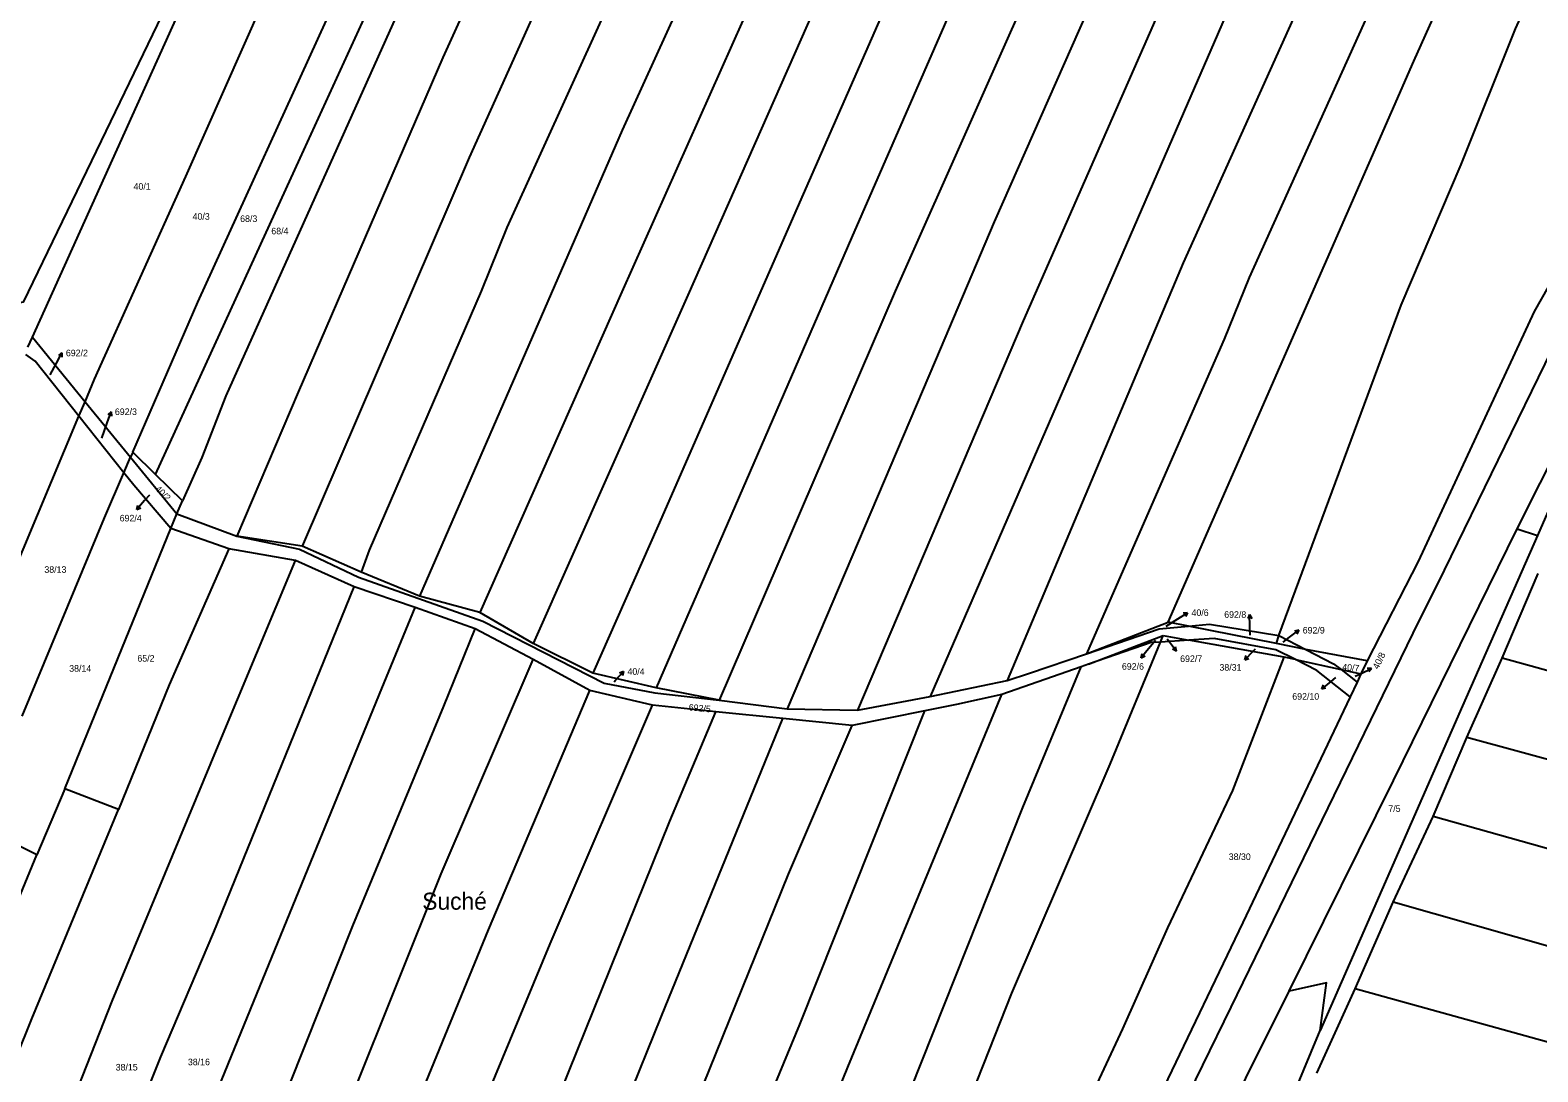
# Model space of a CAD drawing. Extents: x -7483133 to -743169, y -11317770 to -1127091.
# Drawn here: x -746258 to -745868.6, y -1131128.4 to -1130859.4 of the extents above; entities that cross this region are included whole.
import ezdxf

# ---------------------------------------------------------------- set-up
doc = ezdxf.new("R2010")
doc.units = 0
for name, color, linetype in [('Hranice parcel', 7, 'Continuous'), ('Parcelní čísla', 7, 'Continuous'), ('Pop  PČ popisy', 7, 'Continuous')]:
    doc.layers.add(name, color=color, linetype=linetype)

msp = doc.modelspace()

# ---------------------------------------------------------------- linework, layer by layer
at = {"layer": 'Hranice parcel'}
for p, q in [((-746257.43, -1130938.7), (-746218.07, -1130851.43)), ((-746257.43, -1130938.7), (-746218.07, -1130851.43)), ((-745845.23, -1130936.04), (-745868.71, -1130989.88)), ((-746258.58, -1130941.26), (-746257.43, -1130938.7)), ((-746258.58, -1130941.26), (-746257.43, -1130938.7)), ((-746257.43, -1130938.7), (-746243.76, -1130955.41)), ((-746245.4, -1130959.13), (-746243.76, -1130955.41)), ((-746243.76, -1130955.41), (-746232.08, -1130969.68)), ((-746275.51, -1131030.97), (-746245.4, -1130959.13)), ((-746233.82, -1130973.73), (-746245.4, -1130959.13)), ((-746231.52, -1130968.38), (-746232.08, -1130969.68)), ((-746225.59, -1130974.19), (-746231.52, -1130968.38)), ((-746233.82, -1130973.73), (-746232.08, -1130969.68)), ((-746232.08, -1130969.68), (-746220.11, -1130984.31)), ((-746218.64, -1130981), (-746225.59, -1130974.19)), ((-746220.11, -1130984.31), (-746218.64, -1130981)), ((-746249.08, -1131055.3), (-746221.66, -1130988.08)), ((-746221.66, -1130988.08), (-746220.11, -1130984.31)), ((-746206.72, -1130993.33), (-746221.66, -1130988.08)), ((-746220.11, -1130984.31), (-746204.63, -1130990.11)), ((-746187.79, -1130992.68), (-746204.63, -1130990.11)), ((-745873.92, -1130988.21), (-745868.71, -1130989.88)), ((-746189.47, -1130996.38), (-746206.72, -1130993.33)), ((-746172.51, -1130999.37), (-746187.79, -1130992.68)), ((-746174.36, -1131003.15), (-746189.47, -1130996.38)), ((-746157.46, -1131005.59), (-746172.51, -1130999.37)), ((-745877.83, -1131021.56), (-745868.53, -1130999.77)), ((-746158.58, -1131008.54), (-746174.36, -1131003.15)), ((-746141.88, -1131009.81), (-746157.46, -1131005.59)), ((-746143.06, -1131014.03), (-746158.58, -1131008.54)), ((-746128.13, -1131017.8), (-746141.88, -1131009.81)), ((-746128.09, -1131021.91), (-746143.06, -1131014.03)), ((-745985.17, -1131020.45), (-745964.11, -1131012.31)), ((-745958.88, -1131013.33), (-745964.11, -1131012.31)), ((-745936.14, -1131017.79), (-745958.88, -1131013.33)), ((-746112.7, -1131025.49), (-746128.13, -1131017.8)), ((-745984.64, -1131023.14), (-745965.38, -1131015.77)), ((-745966.08, -1131017.43), (-745965.38, -1131015.77)), ((-745958.8, -1131016.95), (-745966.08, -1131017.43)), ((-745965.38, -1131015.77), (-745958.8, -1131016.95)), ((-745934.1, -1131021.36), (-745958.8, -1131016.95)), ((-745936.14, -1131017.79), (-745935.5, -1131015.73)), ((-745928.53, -1131019.33), (-745936.14, -1131017.79)), ((-745935.5, -1131015.73), (-745928.53, -1131019.33)), ((-745912.67, -1131022.25), (-745928.53, -1131019.33)), ((-746113.48, -1131029.98), (-746128.09, -1131021.91)), ((-745984.64, -1131023.14), (-745986.56, -1131023.8)), ((-745931.24, -1131021.98), (-745934.1, -1131021.36)), ((-745931.24, -1131021.98), (-745919.43, -1131024.53)), ((-745912.67, -1131022.25), (-745914.31, -1131025.61)), ((-745886.94, -1131042.08), (-745877.83, -1131021.56)), ((-745753.49, -1131055.99), (-745877.83, -1131021.56)), ((-746096.35, -1131029.25), (-746112.7, -1131025.49)), ((-745986.56, -1131023.8), (-746007.08, -1131031)), ((-745919.43, -1131024.53), (-745914.31, -1131025.61)), ((-745919.43, -1131024.53), (-745915.31, -1131027.82)), ((-745914.31, -1131025.61), (-745915.31, -1131027.82)), ((-746097.27, -1131033.75), (-746113.48, -1131029.98)), ((-746080.02, -1131032.46), (-746096.35, -1131029.25)), ((-746025.56, -1131031.47), (-746005.67, -1131027.4)), ((-745915.31, -1131027.82), (-745917.09, -1131031.6)), ((-746080.96, -1131035.48), (-746097.27, -1131033.75)), ((-746080.02, -1131032.46), (-746062.49, -1131034.7)), ((-746062.49, -1131034.7), (-746044.37, -1131035)), ((-746044.37, -1131035), (-746025.56, -1131031.47)), ((-746063.64, -1131037.14), (-746080.96, -1131035.48)), ((-746045.68, -1131039.01), (-746063.64, -1131037.14)), ((-746026.94, -1131035.21), (-746045.68, -1131039.01)), ((-745895.67, -1131062.5), (-745886.94, -1131042.08)), ((-745759.13, -1131076.92), (-745886.94, -1131042.08)), ((-746249.08, -1131055.3), (-746256.26, -1131072.39)), ((-746235.16, -1131060.66), (-746249.08, -1131055.3)), ((-746256.26, -1131072.39), (-746271.75, -1131064.63)), ((-745905.99, -1131084.62), (-745895.67, -1131062.5)), ((-745915.82, -1131106.97), (-745905.99, -1131084.62)), ((-745925.69, -1131128.75), (-745915.82, -1131106.97))]:
    msp.add_line(p, q, dxfattribs=at)
for points in [[(-746057.93, -1130494.49), (-746062.35, -1130503.85), (-746105.8, -1130595.89), (-746150.91, -1130696.46), (-746187.79, -1130776.59), (-746204.67, -1130815.53), (-746239.66, -1130888), (-746259.77, -1130929.63), (-746291.45, -1130936.17), (-746319.35, -1130949.08), (-746354.98, -1130960.28), (-746376.11, -1130970.56), (-746387.96, -1130978.54), (-746402.31, -1131007.87)], [(-745988.77, -1130503.13), (-745995.08, -1130516.39), (-745997.19, -1130523.51), (-746049.14, -1130639.52), (-746123.64, -1130805.21), (-746151.44, -1130866.52), (-746188.8, -1130952.9), (-746204.63, -1130990.11)], [(-745905.82, -1130502.98), (-745936.28, -1130576.56), (-745953.93, -1130620.89), (-745970.34, -1130658.04), (-745995.29, -1130715.64), (-746045.19, -1130830.57), (-746088.14, -1130927.89), (-746128.13, -1131017.8)], [(-745887.15, -1130503.63), (-745923.53, -1130591.37), (-745959.19, -1130674.9), (-746016.83, -1130807.21), (-746059.9, -1130905.32), (-746095.78, -1130987.36), (-746112.7, -1131025.49)], [(-745926.14, -1130512.41), (-745967.04, -1130611.55), (-746021.26, -1130737.58), (-746043.13, -1130788.29), (-746062.62, -1130831.37), (-746105.23, -1130926.97), (-746141.88, -1131009.81)], [(-745980.78, -1130526.25), (-746032.05, -1130640.66), (-746070.33, -1130726.35), (-746077.16, -1130742.76), (-746105.64, -1130805.67), (-746144.6, -1130892.27), (-746187.79, -1130992.68)], [(-745791.08, -1130527.19), (-745831.43, -1130625.32), (-745874.95, -1130725.59), (-745922.77, -1130836.35), (-745960.25, -1130919.53), (-746005.67, -1131027.4)], [(-745967.15, -1130533.6), (-746000.77, -1130612.35), (-746045.43, -1130711.03), (-746110.07, -1130855.92), (-746134.91, -1130910.39), (-746141.52, -1130926.8), (-746170.42, -1130993.72), (-746172.51, -1130999.37)], [(-745773.63, -1130535.26), (-745815.04, -1130634.22), (-745867.31, -1130750.3), (-745911.69, -1130853.44), (-745943.14, -1130923.26), (-745949.61, -1130939.2), (-745975.07, -1130997.24), (-745985.17, -1131020.45)], [(-745953.14, -1130537.93), (-745968.63, -1130575.77), (-745981.5, -1130606.76), (-746004.63, -1130659.52), (-746060.33, -1130785.21), (-746079.82, -1130829.66), (-746105.11, -1130885.27), (-746123.45, -1130927.43), (-746157.46, -1131005.59)], [(-745964.11, -1131012.31), (-745900.64, -1130867.39), (-745852.82, -1130760.67), (-745807.73, -1130663.28), (-745792.94, -1130627.22), (-745768.53, -1130565.89), (-745761.1, -1130549.07)], [(-745935.5, -1131015.73), (-745903.95, -1130930.45), (-745888.44, -1130894.11), (-745874.37, -1130859.06), (-745863.31, -1130834.5), (-745853.97, -1130814.96), (-745857.13, -1130813.66), (-745812.91, -1130714.98), (-745776.58, -1130632.53), (-745768.53, -1130612.27), (-745747.96, -1130556.83)], [(-745915.1, -1130611.67), (-745924.78, -1130634.57), (-745946.55, -1130684.83), (-745982.43, -1130767.68), (-746045.88, -1130913.08), (-746096.35, -1131029.25)], [(-745901.39, -1130622.72), (-745949.75, -1130733.92), (-745994.18, -1130835.79), (-746034.56, -1130926.83), (-746080.02, -1131032.46)], [(-745887.26, -1130631.72), (-745912.55, -1130689.83), (-745963.13, -1130805.14), (-746009.04, -1130908.95), (-746024.19, -1130944.61), (-746062.49, -1131034.7)], [(-745873.05, -1130641.36), (-745913.49, -1130733.24), (-745954.61, -1130827.58), (-746001.53, -1130934.46), (-746044.37, -1131035)], [(-745858.92, -1130647.52), (-745897.83, -1130737.31), (-745959.11, -1130878.37), (-746025.56, -1131031.47)], [(-746243.76, -1130955.41), (-746241.39, -1130949.57), (-746217.8, -1130897.25), (-746197.84, -1130852.2)], [(-746231.52, -1130968.38), (-746214.66, -1130929.63), (-746179.66, -1130852.89)], [(-746225.59, -1130974.19), (-746188.23, -1130892.48), (-746170.29, -1130853.24)], [(-746162.43, -1130853.54), (-746207.49, -1130953.81), (-746213.64, -1130969.77), (-746218.64, -1130981)], [(-745848.33, -1130906.51), (-745859.5, -1130930.22), (-745865.08, -1130942.05), (-745892.81, -1130998.91), (-745900.93, -1131015.11), (-745947.93, -1131111.72), (-746021.05, -1131261.49)], [(-745848.33, -1130906.51), (-745855.86, -1130913.35), (-745865.92, -1130925.72), (-745869.61, -1130932.09), (-745899.55, -1130996.61), (-745912.67, -1131022.25)], [(-745873.92, -1130988.21), (-745856.25, -1130953.03), (-745852.08, -1130945.69), (-745845.23, -1130936.04)], [(-746245.4, -1130959.13), (-746256.67, -1130944.92), (-746259.08, -1130943.14)], [(-746260.09, -1131036.56), (-746238.81, -1130985.36), (-746233.82, -1130973.73)], [(-746221.66, -1130988.08), (-746231.26, -1130976.95), (-746233.82, -1130973.73)], [(-746204.63, -1130990.11), (-746188.4, -1130993.48), (-746173.23, -1131000.65), (-746141.09, -1131012.01), (-746109.79, -1131028.02), (-746096.65, -1131030.53), (-746080.02, -1131032.46)], [(-745932.85, -1131107.56), (-745905.92, -1131053.19), (-745873.92, -1130988.21)], [(-745868.71, -1130989.88), (-745888.07, -1131033.94), (-745924.82, -1131117.75)], [(-746206.72, -1130993.33), (-746222.06, -1131028.52), (-746235.16, -1131060.66)], [(-746308.05, -1131285.05), (-746304.24, -1131275.89), (-746279.18, -1131217.54), (-746236.8, -1131110.19), (-746209.41, -1131044.25), (-746189.47, -1130996.38)], [(-746291.79, -1131289.65), (-746277.81, -1131256.06), (-746254.63, -1131200.27), (-746224.27, -1131124.55), (-746210.55, -1131092.34), (-746174.36, -1131003.15)], [(-746275.86, -1131294.65), (-746245.14, -1131221.53), (-746230.49, -1131185.54), (-746225.93, -1131173), (-746198.59, -1131106.22), (-746167.15, -1131029.42), (-746158.58, -1131008.54)], [(-746260.41, -1131299.59), (-746247.54, -1131268.82), (-746226.35, -1131218.91), (-746207.71, -1131173.69), (-746174.67, -1131090.73), (-746151.2, -1131033.98), (-746143.06, -1131014.03)], [(-745985.17, -1131020.45), (-745966.4, -1131014.05), (-745958.88, -1131013.33)], [(-745958.88, -1131013.33), (-745953.38, -1131012.81), (-745935.5, -1131015.73)], [(-746097.49, -1131342.07), (-746095.99, -1131337.89), (-746049.56, -1131222.27), (-746019.32, -1131145.53), (-746004.47, -1131108.13), (-745979.09, -1131048.94), (-745966.08, -1131017.43)], [(-745966.08, -1131017.43), (-745968.52, -1131017.59), (-745984.64, -1131023.14)], [(-745931.24, -1131021.98), (-745936.27, -1131019.43), (-745952.24, -1131016.51), (-745958.8, -1131016.95)], [(-745928.53, -1131019.33), (-745921.37, -1131023.03), (-745919.43, -1131024.53)], [(-746244.6, -1131305.36), (-746209.14, -1131220.17), (-746151.88, -1131077.28), (-746128.09, -1131021.91)], [(-746005.67, -1131027.4), (-745999.91, -1131025.48), (-745985.17, -1131020.45)], [(-745984.27, -1131135.42), (-745975.82, -1131117.29), (-745964.16, -1131091.23), (-745947.42, -1131055.74), (-745934.1, -1131021.36)], [(-745917.09, -1131031.6), (-745925.67, -1131024.8), (-745931.24, -1131021.98)], [(-746118.56, -1131349.89), (-746087.87, -1131274.28), (-746030.57, -1131132.93), (-746001.63, -1131060.16), (-745986.56, -1131023.8)], [(-746229, -1131310.73), (-746207.2, -1131257.32), (-746164.14, -1131151.57), (-746139.64, -1131091.74), (-746125.06, -1131057.44), (-746113.48, -1131029.98)], [(-746135.52, -1131345.72), (-746110.07, -1131284.99), (-746090.39, -1131234.71), (-746046.86, -1131127.25), (-746007.08, -1131031)], [(-746007.08, -1131031), (-746018.8, -1131033.56), (-746026.94, -1131035.21)], [(-746214.34, -1131315.99), (-746200.4, -1131282.56), (-746179.52, -1131231.91), (-746156.17, -1131173.57), (-746123.7, -1131095.4), (-746097.27, -1131033.75)], [(-745917.09, -1131031.6), (-745944.81, -1131089.83), (-745965.24, -1131132.37)], [(-746197.7, -1131321.83), (-746183.9, -1131293.06), (-746162.26, -1131234.49), (-746123.3, -1131139.23), (-746092.84, -1131063.68), (-746080.96, -1131035.48)], [(-746180.71, -1131328.03), (-746179.23, -1131324.5), (-746172.17, -1131304.33), (-746153.94, -1131253.29), (-746123.07, -1131183.78), (-746094.92, -1131114.05), (-746063.64, -1131037.14)], [(-746151.18, -1131340.19), (-746120.98, -1131267.76), (-746085.94, -1131180.71), (-746059.22, -1131116.2), (-746026.94, -1131035.21)], [(-746165.85, -1131333.99), (-746111.01, -1131199.04), (-746085.94, -1131136.15), (-746062.14, -1131077.35), (-746045.68, -1131039.01)], [(-746324.3, -1131279.77), (-746300.83, -1131222.1), (-746257.54, -1131114.75), (-746235.16, -1131060.66)], [(-745768.13, -1131098.66), (-745821.65, -1131083.28), (-745895.67, -1131062.5)], [(-746339.86, -1131274.71), (-746326.21, -1131243), (-746286.91, -1131146.58), (-746256.26, -1131072.39)], [(-745778.72, -1131121.55), (-745832.47, -1131105.57), (-745905.99, -1131084.62)], [(-746045.83, -1131334.47), (-746013.98, -1131270.95), (-746005.43, -1131253.32), (-745955.19, -1131152.53), (-745932.85, -1131107.56)], [(-745924.82, -1131117.75), (-745923.23, -1131105.47), (-745932.85, -1131107.56)], [(-745788.57, -1131143.21), (-745846.49, -1131126.17), (-745915.82, -1131106.97)], [(-746014.99, -1131339.08), (-746003.38, -1131310.83), (-745982.75, -1131257.85), (-745970.5, -1131228.02), (-745967.46, -1131219.51), (-745946.05, -1131166.46), (-745935.62, -1131143.65), (-745924.82, -1131117.75)]]:
    msp.add_lwpolyline(points, dxfattribs=at)
at = {"layer": 'Pop  PČ popisy'}
for p, q in [((-746251.2, -1130945.42), (-746249.79, -1130942.77)), ((-746249.79, -1130942.77), (-746250.7, -1130943.42)), ((-746249.79, -1130942.77), (-746249.82, -1130943.89)), ((-746252.83, -1130948.46), (-746251.2, -1130945.42)), ((-746239.47, -1130964.76), (-746238.1, -1130960.8)), ((-746238.1, -1130960.8), (-746237.12, -1130957.96)), ((-746237.12, -1130957.96), (-746237.92, -1130958.75)), ((-746237.12, -1130957.96), (-746236.98, -1130959.07)), ((-746227.22, -1130979.47), (-746228.47, -1130980.9)), ((-746228.47, -1130980.9), (-746230.44, -1130983.17)), ((-746230.44, -1130983.17), (-746230.16, -1130982.08)), ((-746230.44, -1130983.17), (-746229.4, -1130982.74)), ((-745964.58, -1131013.31), (-745961.61, -1131011.45)), ((-745961.61, -1131011.45), (-745959.07, -1131009.86)), ((-745959.07, -1131009.86), (-745960.18, -1131009.97)), ((-745959.07, -1131009.86), (-745959.65, -1131010.81)), ((-745943.05, -1131010.33), (-745943.54, -1131011.34)), ((-745943, -1131013.33), (-745943.05, -1131010.33)), ((-745943.05, -1131010.33), (-745942.53, -1131011.32)), ((-745942.95, -1131015.67), (-745943, -1131013.33)), ((-745932.74, -1131016.19), (-745930.34, -1131014.38)), ((-745930.34, -1131014.38), (-745931.44, -1131014.59)), ((-745930.34, -1131014.38), (-745930.84, -1131015.39)), ((-745969.15, -1131019.17), (-745971.08, -1131021.47)), ((-745967.33, -1131017.01), (-745969.15, -1131019.17)), ((-745964.34, -1131016.6), (-745963.79, -1131017.35)), ((-745963.79, -1131017.35), (-745961.98, -1131019.75)), ((-745961.98, -1131019.75), (-745962.99, -1131019.25)), ((-745961.98, -1131019.75), (-745962.19, -1131018.65)), ((-745941.6, -1131019.24), (-745942.2, -1131019.86)), ((-745934.39, -1131017.43), (-745932.74, -1131016.19)), ((-745971.08, -1131021.47), (-745970.82, -1131020.38)), ((-745971.08, -1131021.47), (-745970.05, -1131021.02)), ((-745942.2, -1131019.86), (-745944.29, -1131022.02)), ((-745944.29, -1131022.02), (-745943.95, -1131020.95)), ((-745944.29, -1131022.02), (-745943.23, -1131021.65)), ((-746106.79, -1131027.24), (-746104.74, -1131025.04)), ((-746104.74, -1131025.04), (-746105.79, -1131025.44)), ((-746104.74, -1131025.04), (-746105.06, -1131026.12)), ((-745920.86, -1131026.57), (-745922.11, -1131027.6)), ((-745915.76, -1131026.28), (-745914.29, -1131025.56)), ((-745914.29, -1131025.56), (-745911.59, -1131024.24)), ((-745911.59, -1131024.24), (-745912.71, -1131024.23)), ((-745911.59, -1131024.24), (-745912.27, -1131025.13)), ((-746107.2, -1131027.69), (-746106.79, -1131027.24)), ((-745922.11, -1131027.6), (-745924.44, -1131029.49)), ((-745924.44, -1131029.49), (-745923.98, -1131028.47)), ((-745924.44, -1131029.49), (-745923.35, -1131029.25))]:
    msp.add_line(p, q, dxfattribs=at)

# ---------------------------------------------------------------- texts
at = {"layer": 'Parcelní čísla'}
for s, p in [('40/1', (-746231.3, -1130900.63)), ('40/3', (-746216.05, -1130908.38)), ('68/3', (-746203.77, -1130908.96)), ('68/4', (-746195.72, -1130912.15)), ('692/2', (-746248.78, -1130943.63)), ('692/3', (-746236.12, -1130958.81)), ('692/4', (-746234.88, -1130986.29)), ('38/13', (-746254.33, -1130999.56)), ('40/6', (-745958.07, -1131010.71)), ('692/8', (-745949.62, -1131011.18)), ('692/9', (-745929.35, -1131015.23)), ('65/2', (-746230.31, -1131022.5)), ('692/6', (-745976.04, -1131024.58)), ('692/7', (-745961, -1131022.59)), ('38/31', (-745950.85, -1131024.83)), ('38/14', (-746247.92, -1131025.1)), ('40/4', (-746103.74, -1131025.9)), ('692/10', (-745932.04, -1131032.33)), ('7/5', (-745907.24, -1131061.32)), ('38/30', (-745948.46, -1131073.73)), ('38/15', (-746235.92, -1131128.08)), ('38/16', (-746217.26, -1131126.72))]:
    msp.add_text(s, height=1.7, dxfattribs=at).set_placement(p)
for s, rotation, p in [('40/2', 316, (-746225.87, -1130978.1)), ('40/7', 355, (-745919.2, -1131024.7)), ('40/8', 64, (-745909.84, -1131024.6)), ('692/5', 355, (-746087.98, -1131035.1))]:
    msp.add_text(s, height=1.7, rotation=rotation, dxfattribs=at).set_placement(p)
at = {"layer": 'Pop  PČ popisy'}
msp.add_text('Suché', height=4.4, dxfattribs=at).set_placement((-746156.74, -1131086.56))

doc.saveas('drawing.dxf')
